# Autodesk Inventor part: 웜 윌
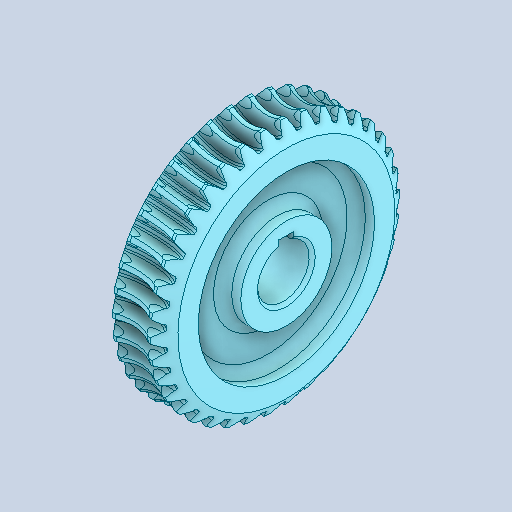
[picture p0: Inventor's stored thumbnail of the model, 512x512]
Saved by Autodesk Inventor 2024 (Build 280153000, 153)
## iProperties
Created: 2026-01
Part Number: 웜 윌
Material: 강철, 합금
Document SubType Name: Modeling
Designer: 2-10
Density: 7.73 g/cm^3
Appearance: 기본값
Author: jhkim
Sending System: Autodesk Inventor 2026
Preprocessor: ST-DEVELOPER v20.1
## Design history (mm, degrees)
node "웜 휠1"
node "솔리드2"
node "솔리드1"
